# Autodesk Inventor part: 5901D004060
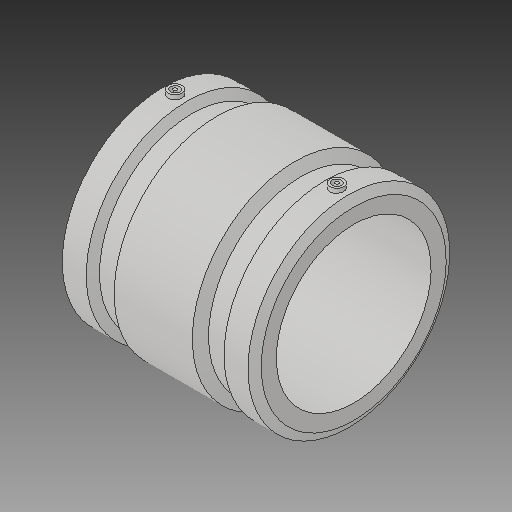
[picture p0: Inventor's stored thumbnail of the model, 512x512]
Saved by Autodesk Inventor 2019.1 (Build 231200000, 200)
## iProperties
Created: 2017-06
Part Number: 5901D004060
Material: Generic
Description: PLASSON COUPLER 6''DIPS
Document SubType Name: Modeling
Designer: KIM
Mass: 96874 g
Surface Area: 34549.7 cm^2
Volume: 96874 cm^3
Density: 1 g/cm^3
Appearance: Default
Author: KIM
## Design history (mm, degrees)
derived "5901D.ipt"
feature "Solid1::5901D.ipt"
tag "TaggingFeature1"
body "Solid1"
other parameters: "d13" = 212.09, "d15" = 104.394, "d16" = 104.394, "d17" = 168, "d22" = 228.092, "d23" = 223.012, "d24" = 200.72096, "d25" = 150 deg, "d26" = 84.836, "d27" = 120 deg, "d29" = 114.046, "d35" = 15, "d39" = 0, "d40" = 4, "d41" = 14, "d42" = 0, "d44" = 36.5379, "d45" = 168, "d47" = 0, "d48" = 109.48416, "d49" = 36.5379, "d50" = 60 deg, "d57" = 65.786, "d58" = 36.5379, "d62" = 168, "d65" = 282.448, "d67" = 5.27613, "d68" = 21.15863, "d69" = 21.80789, "d70" = 21.71015, "d71" = 20.5722, "d72" = 20.71531, "d73" = 561.2638, "d76" = 84.836, "d77" = 200.72096, "d_" = 168, "L_" = 212.09, "L_1" = 104.394, "D_" = 223.012, "A_" = 114.046, "A_1" = 25.4, "d60" = 187.96
